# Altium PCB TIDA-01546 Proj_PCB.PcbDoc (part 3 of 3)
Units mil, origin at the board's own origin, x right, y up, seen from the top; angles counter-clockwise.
Board outline 2500 x 2000 mil, 2 copper layers (Top Layer, Bottom Layer), stack 62 mil thick; 176 components, 113 nets, 564 pads, 250 vias.
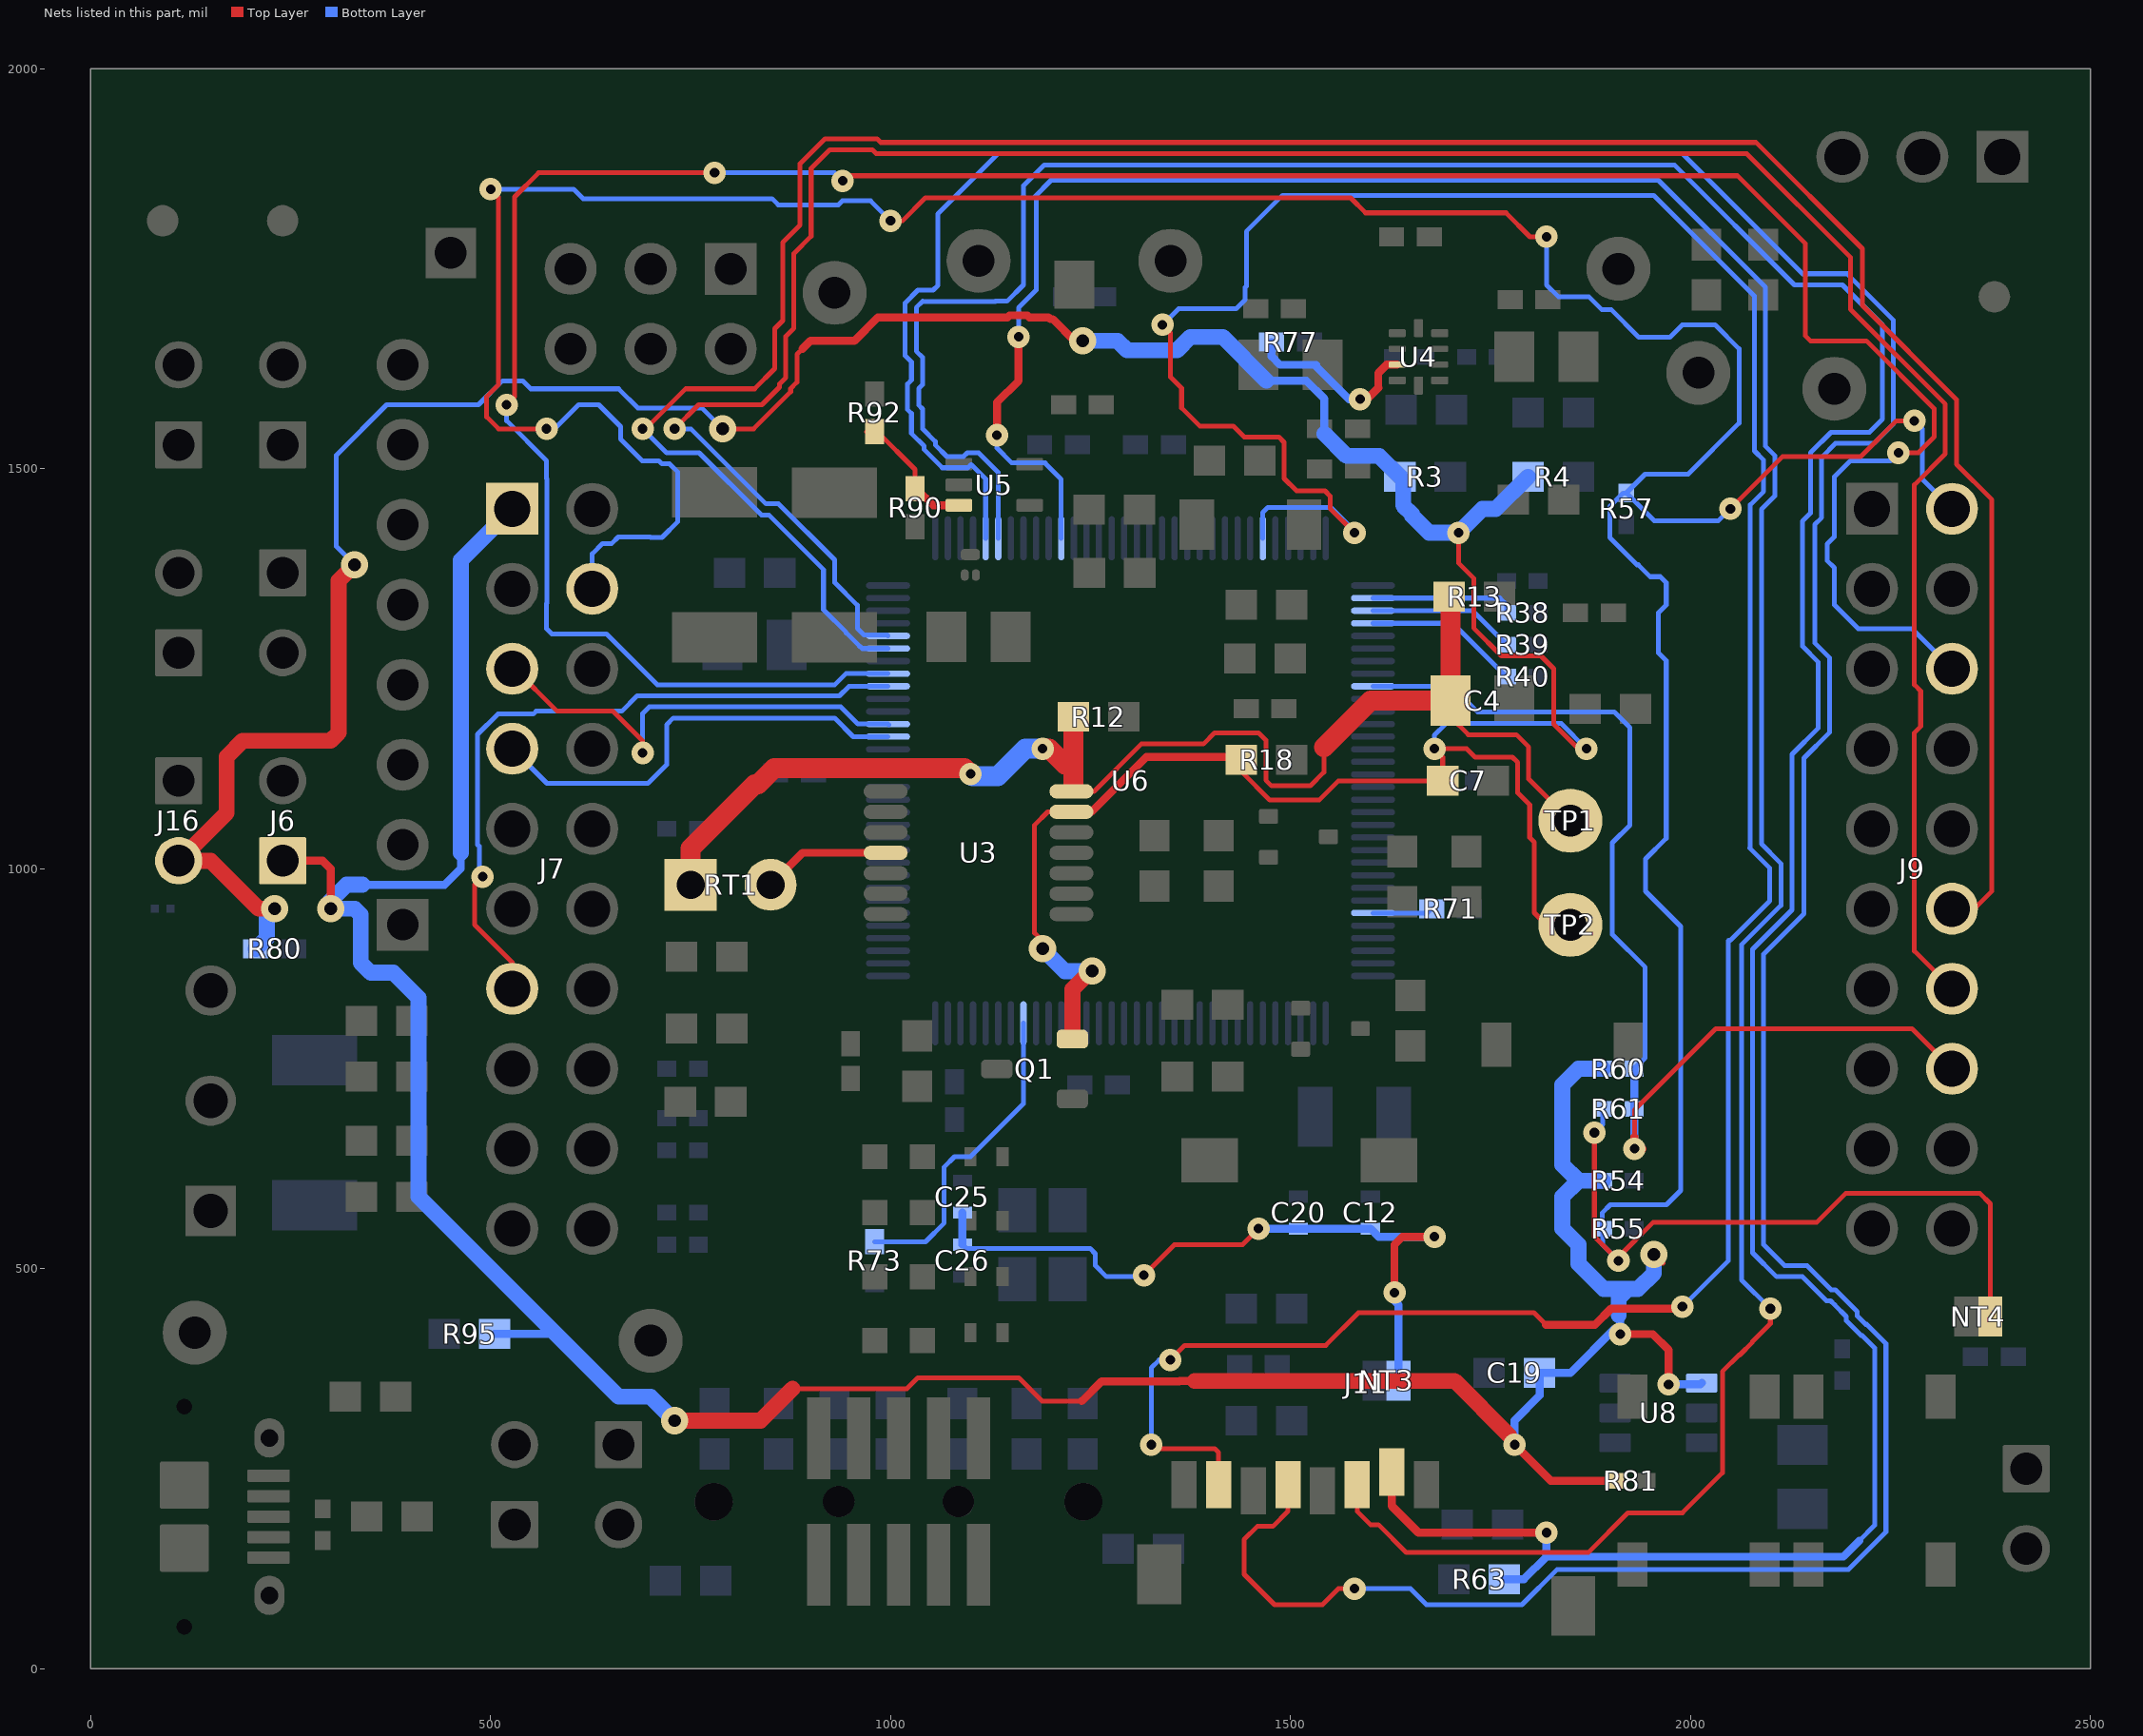
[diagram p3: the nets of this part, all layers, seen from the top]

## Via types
v1: diameter 28, hole 12, Top Layer to Bottom Layer, 217 vias
v2: diameter 34, hole 16, Top Layer to Bottom Layer, 30 vias
v3: diameter 50, hole 28, Top Layer to Bottom Layer, 3 vias

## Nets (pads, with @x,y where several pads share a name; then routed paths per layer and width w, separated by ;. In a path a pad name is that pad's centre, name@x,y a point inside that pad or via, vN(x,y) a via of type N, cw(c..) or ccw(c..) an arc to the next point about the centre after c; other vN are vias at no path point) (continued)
NetR38_1: R38.1 U6.34 | length 180.4
  Bottom Layer w6: U6.34@1603.15,1338.35 1761.65,1338.35 1770.32,1329.68 R38.1@1770.32,1320
NetR39_2: R39.2 U6.35 | length 184.8
  Bottom Layer w6: U6.35@1603.15,1322.6 1727.72,1322.6 R39.2@1770.31,1280
NetR40_1: R40.1 U6.36 | length 194.9
  Bottom Layer w6: U6.36@1603.15,1306.85 1703.15,1306.85 1770,1240 R40.1@1770.32,1240
NetR71_1: R71.1 U6.59 | length 75.4
  Bottom Layer w6: U6.59@1603.15,944.65 1671.02,944.65 R71.1@1676.38,950
NetR73_1: R73.1 U6.89 | length 399.3
  Bottom Layer w6: R73.1@980,533.62 1043.62,533.62 1067.13,557.13 1067.13,627.13 1080,640 1100,640 1166.14,706.14 U6.89@1166.14,806.85
NetR76_1: R77.2 U4.3 | length 223.4
  Top Layer w10: v1@1590,1590 1598.75,1590 1609.92,1601.17 1609.72,1601.37 1609.72,1619.57 1620.16,1630.01 1620.16,1630.16 U4.3@1633.43,1630.16
  Bottom Layer w10: R77.2@1476.38,1658.52 1476.38,1640.49 1486.87,1630 1532.35,1630 1532.35,1627.65 1573,1587 v1(1587,1587)
NetR90_2: R90.2 R92.2 U5.3 | length 167.7
  Top Layer w6: R92.2@970,1546.38 983.46,1546.38 1030.63,1499.21 R90.2@1030.63,1474.99
  Top Layer w10: R90.2@1030.63,1474.99 1032.6,1474.99 1053.18,1454.41 U5.3@1085.39,1454.41
NetRT1_2: RT1.2 U3.11 | length 160.4
  Top Layer w10: RT1.2@850,980 889.99,1019.99 U3.11@993.85,1019.99
REG25: C4.2 R12.1 R13.1 RT1.1 TP1.1 U3.7 | length 1684.1
  Top Layer w6: U3.7@1226.13,1096.76 1254.32,1096.76 1313.42,1155.87 1391.05,1155.87 1405.18,1170 1460,1170 1469.22,1160.78 1469.22,1110.78 1476.41,1103.59 1524.65,1103.59 1541.71,1120.66 1541.71,1151.71 ; C4.2@1700,1204.69 1700,1190 1722.37,1167.63 1782.37,1167.63 1797.88,1152.12 1797.88,1112.12 TP1.1@1850,1060
  Top Layer w10: 1218.5,1130 1228.5,1140
  Top Layer w25: RT1.1@750,980 750,1025.13 830.5,1105.63 834.24,1105.63 854.61,1126 1092.42,1126 v1(1100,1118.42) ; v1(1190,1150) 1198.5,1150 1218.5,1130 ; U3.7@1228.5,1102.78 1228.5,1140 R12.1@1228.5,1190 ; 1541.71,1151.71 1600,1210 C4.2@1700,1210 ; C4.2@1700,1204.69 C4.2@1700,1210 ; R13.1@1700,1340 C4.2@1700,1210
  Bottom Layer w25: v1(1100,1118.42) 1102.79,1115.63 1134.24,1115.63 1168.61,1150 v1(1190,1150)
REGIN: C7.2 J16.2 Q1.2 R3.1 R4.1 R18.1 R80.1 TP2.1 U3.6 | length 4627.6
  Top Layer w6: v2(790,1550) 828.75,1550 875.13,1596.38 875.13,1600.3 883,1608.18 883,1643 890,1650 ; v2(1190,900) 1190,909.6 1180,919.6 1180,1054.57 1196.61,1071.17 U3.6@1226.13,1071.17 ; R18.1@1438.66,1136.28 1438.66,1121.34 1474.28,1085.72 1535.72,1085.72 1560,1110 C7.2@1690.32,1110 1690.32,1139.68 v1(1680,1150) 1720.38,1150 1730.8,1139.57 1777.5,1139.57 1784.01,1133.07 1784.01,1095.12 1799.13,1080 1799.13,1038.93 1804.87,1033.18 1804.87,945.13 1820.18,929.82 TP2.1@1849.88,929.82 ; v1(1710,1420) 1710,1382.27 1729.06,1363.2 1729.06,1300.94 1763.78,1266.22 1812.99,1266.22 1829.1,1250.11 1829.1,1180.9 1860,1150 v1(1870,1150)
  Top Layer w10: 890,1650 900,1660 954.92,1660 984.18,1689.25 1146.25,1689.25 1148.87,1691.87 1171.13,1691.87 1173.75,1689.25 1197.54,1689.25 1199.67,1687.13 1202.87,1687.13 1230,1660 v2(1240,1660) ; U3.6@1226.13,1071.17 1251.17,1071.17 1320,1140 R18.1@1440,1140 ; v2@1250,871.97 v2(1251.97,871.97)
  Top Layer w20: v2(230,950) 210,950 150,1010 J16.2@110,1010 170,1070 170,1140 190,1160 300,1160 310,1170 310,1360 v2(330,1380) ; Q1.2@1227.24,787.09 1227.24,849.21 v2@1250,871.97
  Bottom Layer w6: v2(330,1380) 307.13,1402.87 307.13,1517.13 370,1580 484.82,1580 514.82,1610 540.04,1610 550.04,1600 660,1600 683.87,1576.13 763.87,1576.13 v2(790,1550) ; v1(1680,1150) 1680,1167 1694.46,1181.46 1838.54,1181.46 v1(1870,1150)
  Bottom Layer w10: 1470,1610 1520,1610 1542.28,1587.72 1542.28,1543.94
  Bottom Layer w20: R80.1@206.38,900 220,913.62 220,940 v2(230,950) ; v2(1190,900) 1218.03,871.97 v2(1251.97,871.97) ; v2(1240,1660) 1283.97,1660 1295.85,1648.13 1358.13,1648.13 1374.87,1664.87 1415.13,1664.87 1470,1610 ; 1542.28,1543.94 1570.18,1516.04 1610.81,1516.04 R3.1@1636.85,1490 1640.87,1485.98 1640.87,1454.2 1651.87,1443.2 1651.87,1441.54 1673.42,1420 v1(1710,1420) 1740,1450 1756.85,1450 R4.1@1796.85,1490
RESET: J9.16 R60.1 R61.1 U6.41 | length 1419.3
  Top Layer w6: 1930,665 1930,698.35 2031.65,800 2277,800 J9.16@2327,750
  Top Layer w10: 1930,665 v1(1930,650) v1@1940,650
  Bottom Layer w6: U6.41@1603.15,1228.11 1701.89,1228.11 1733.87,1196.13 1904.63,1196.13 1924.5,1176.25 1924.5,1054.5 1902.38,1032.38 1902.38,918 1943.46,876.91 1943.46,763.78 R60.1@1929.69,750
  Bottom Layer w10: R60.1@1929.69,750 R61.1@1929.68,700 1929.68,680.32 1930,680 v1(1930,650)
SD_SSI3_CLK: J11.5 U6.5 | length 4546
  Top Layer w6: J11.5@1496.77,230 1496.77,196.77 1477.87,177.87 1458.45,177.87 1442.13,161.55 1442.13,117.87 1480,80 1540,80 1560,100 v1(1580,100)
  Bottom Layer w6: U6.5@1118.9,1413.15 1118.9,1487.23 1100.86,1505.27 1096.84,1501.25 1064.74,1501.25 1042.04,1523.95 1042.04,1528.34 1026.13,1544.25 1026.13,1569.08 1021.25,1573.95 1021.25,1606.05 1026.13,1610.92 1026.13,1633.49 1018.25,1641.37 1018.25,1707.29 1034.25,1723.29 1053.29,1723.29 1059.13,1729.13 1059.13,1818.75 1134.56,1894.18 1989.69,1894.18 2140,1743.87 2195.75,1743.87 2253.87,1685.75 2253.87,1556.25 2229.44,1531.82 2181.44,1531.82 2164.05,1514.43 2164.05,1438.98 2155.4,1430.33 2155.4,1282.39 2173.87,1263.92 2173.87,1170.21 2141.83,1138.17 2141.83,943.64 2091.62,893.42 2091.62,530 2117.75,503.87 2145.75,503.87 2175.87,473.75 2181.05,473.75 2186.05,468.75 2208.75,446.05 2208.75,440.87 2219.19,430.43 2220.48,430.43 2244.46,406.45 2244.46,170.79 2197.8,124.13 1833.49,124.13 1789.36,80 1670,80 1650,100 v1(1580,100)
SD_SSI3_CS: J11.2 R63.2 U6.6 | length 4271.5
  Top Layer w10: J11.2@1626.69,245.75 1626.69,203.31 1660,170 v1(1820,170)
  Bottom Layer w6: U6.6@1134.65,1413.15 1134.65,1495.35 1110,1520 1095.96,1520 1091.09,1515.13 1070.48,1515.13 1055.91,1529.7 1055.91,1534.09 1040,1550 1040,1574.82 1035.13,1579.7 1035.13,1600.3 1040,1605.18 1040,1639.24 1032.13,1647.12 1032.13,1701.55 1040,1709.42 1040.29,1709.13 1131.07,1709.13 1131.37,1709.42 1145.55,1709.42 1166.13,1730 1166.13,1853.87 1192.25,1880 1980,1880 2130,1730 2190,1730 2240,1680 2240,1562 2223.69,1545.69 2175.69,1545.69 2150.18,1520.18 2150.18,1444.78 2140,1434.6 2140,1278.18 2160,1258.18 2160,1175.95 2127.08,1143.04 2127.08,948.51 2077.75,899.17 2077.75,520 2107.75,490 2140,490 2170.13,459.87 2175.3,459.87 2180.3,454.87 2194.87,440.3 2194.87,435.13 2213.44,416.56 2214.74,416.56 2230.59,400.71 2230.59,179.37 2211.22,160
  Bottom Layer w10: R63.2@1767.49,111.89 1791.89,111.89 1820,140 ; v1(1820,170) 1820,140 ; 2211.22,160 2191.22,140 1820,140
SD_SSI3_DAT0: J11.3 U6.11 | length 3600.2
  Top Layer w6: v1@1160,1660 v1(1160,1665) ; J11.3@1583.39,230 1583.39,196.61 1600,180 1610,180 1644.87,145.13 1872.33,145.13 1922.02,194.82 1990,194.82 2040,244.82 2040,371.41 2060.72,392.13 2061.55,392.13 2077.87,408.45 2077.87,409.28 2100,431.41 v1(2100,450)
  Top Layer w10: v1(1133,1542.02) 1133,1583 1160,1610 v1@1160,1660
  Bottom Layer w6: v1(1133,1542.02) 1133,1525.83 1151.51,1507.32 1193.53,1507.32 1193.53,1506.47 1213.39,1486.61 U6.11@1213.39,1413.15 ; v1(1160,1665) 1160,1701.42 1182,1723.42 1182,1840 ; 1180,1840 1200.76,1860.76 1960,1860.76 2093.87,1726.88 2093.87,1528.11 2105.39,1516.59 2105.39,1465.86 2088.75,1449.22 2088.75,1031.25 2099.92,1020.08 2099.92,1019.7 2113.21,1006.41 2113.21,954.25 2063.87,904.92 2063.87,486.13 v1(2100,450)
SD_SSI3_DAT1: J11.7 U6.27 | length 3764.8
  Top Layer w6: v1(1325.9,280) 1330.78,275.13 1405.19,275.13 1410.16,270.16 J11.7@1410.16,230 ; v1(1340,1680) 1350,1670 1350,1614.8 1363.87,1600.92 1363.87,1576.13 1386.55,1553.45 1428.44,1553.45 1442.31,1539.57 1485.69,1539.57 1492.06,1533.2 1492.06,1487.94 1507.63,1472.37 1543.09,1472.37 1549.46,1466 1549.46,1450.54 v1(1580,1420) ; v1(1349.67,385.93) 1367.86,404.13 1544.13,404.13 1585,445 1804.34,445 1819.34,430 ; v1@1990,450 v1(1990,452.5)
  Top Layer w10: 1819.34,430 1880.79,430 1900.79,450 v1@1990,450
  Bottom Layer w6: v1(1325.9,280) 1325.9,375.9 1335.93,385.93 v1(1349.67,385.93) ; v1(1340,1680) 1360,1700 1432,1700 1443.5,1711.5 1443.5,1726.95 1444.87,1728.32 1444.87,1796.73 1490,1841.86 1954.07,1841.86 2080,1715.93 2080,1522.36 2091.51,1510.85 2091.51,1471.61 2074.87,1454.96 2074.87,1027.13 2073.87,1026.13 2099.34,1000.66 2099.34,960 2050,910.66 ; U6.27@1465.35,1413.15 1465.35,1445.35 1471.58,1451.58 1550.23,1451.58 v1@1580,1421.81 ; v1(1990,452.5) 2047.5,510 2047.5,910.16 2048,910.66
SPI_CLK: J7.13 U6.120 | length 882.3
  Top Layer w6: v1(490,990) 480,980 480,930 527,883 J7.13@527,850
  Bottom Layer w6: v1(490,990) 485.69,994.31 485.69,1027.96 483.65,1030 483.65,1167.96 509.04,1193.35 553.35,1193.35 557,1197 664,1197 683.13,1216.13 936.13,1216.13 948.11,1228.11 U6.120@996.85,1228.11
SPI_CS1: J9.6 U6.121 | length 3537.4
  Top Layer w6: v1(520,1580) 530,1590 530,1840 560,1870 v1(780,1870) ; v1(940,1860) 946.37,1866.37 2058.91,1866.37 2143.87,1781.41 2143.87,1666.13 2150,1660 2220,1660 2304.87,1575.13 2304.87,1540 2284.87,1520 v1(2260,1520)
  Bottom Layer w6: v1(520,1580) 520,1560 570,1510 570,1487.69 570.35,1487.34 570.35,1332.04 570,1331.69 570,1300 576.65,1293.35 644.96,1293.35 708.31,1230 930.38,1230 944.24,1243.86 U6.121@996.85,1243.86 ; v1(780,1870) 930,1870 v1(940,1860) ; v1(2260,1520) 2250,1510 2200,1510 2180,1490 2180,1415.05 2170.9,1405.95 2170.9,1385.34 2180,1376.25 2180,1330 2210,1300 2277,1300 J9.6@2327,1250
SPI_MISO: J9.14 U6.124 | length 3220.3
  Top Layer w6: v1(730,1550) 760,1580 839.13,1580 861.25,1602.13 861.25,1606.05 869.13,1613.92 869.13,1648.75 869.13,1665.77 879.13,1675.77 879.13,1769.13 900.7,1790.7 900.7,1875.5 923.95,1898.75 977.34,1898.75 981.97,1894.12 2070.4,1894.12 2200,1764.52 2200,1699.62 2318.75,1580.87 2318.75,1518.75 2280,1480 2280,1230 2287.84,1222.16 2287.84,1177.84 2280,1170 2280,897 J9.14@2327,850
  Bottom Layer w6: v1(730,1550) 750.38,1550 844.25,1456.13 860,1456.13 930,1386.13 930,1357.95 958.42,1329.54 958.42,1300.72 967.09,1292.04 995.91,1292.04 U6.124@996.85,1291.1
SPI_MOSI: J9.12 U6.123 | length 3235
  Top Layer w6: v1@693.87,1550 743.87,1600 830,1600 855.25,1625.25 855.25,1675.25 865.25,1685.25 865.25,1782.97 886.82,1804.55 886.82,1881.24 918.2,1912.62 983.09,1912.62 987.72,1907.99 2082.01,1907.99 2215,1775 2215,1704.24 2332.62,1586.62 2332.62,1505.69 2377,1461.31 2377,972 2358,953 J9.12@2330,953
  Bottom Layer w6: v1(690,1550) 720,1520 760.76,1520 838.51,1442.25 847.75,1442.25 916.13,1373.87 916.13,1323.87 944.54,1295.46 944.54,1294.97 961.35,1278.17 961.83,1278.17 964.65,1275.35 U6.123@996.85,1275.35
SYS_GND: J7.4 J9.2 NT4.2 R55.1 R57.1 R61.2 | length 5384.6
  Top Layer w6: v1(500,1849.57) 510,1839.57 510,1605.18 495.13,1590.3 495.13,1564.87 510,1550 v1(570,1550) v1@575.02,1550 ; v1(1000,1810) 1014.82,1810 1043.44,1838.62 1575.25,1838.62 1593.87,1820 1769.52,1820 1799.52,1790 v1(1820,1790) ; v1(1880,670) 1880,540 v1(1910,510) 1910,514.57 1953.25,557.82 2157.82,557.82 2194.48,594.48 2361.72,594.48 2375,581.2 NT4.2@2375,440 ; v1(2050,1450) 2115,1515 2212.62,1515 2257.62,1560 v1(2280,1560)
  Bottom Layer w6: v1(500,1849.57) 603.79,1849.57 615.61,1837.75 851.87,1837.75 859.62,1830 934.82,1830 939.7,1834.87 969.87,1834.87 970,1835 975,1835 v1(1000,1810) v1@990,1810 ; v1(570,1550) 580,1550 610,1580 635.18,1580 662.59,1552.59 662.59,1537.03 689.62,1510 710.38,1510 714.25,1506.13 723.87,1506.13 734.07,1495.93 734.07,1434.07 714.23,1414.23 700,1414.23 699.36,1414.87 659.7,1414.87 651.47,1406.65 640,1406.65 627,1393.65 J7.4@627,1350 J7.4@620,1350 ; v1(1820,1790) 1820,1730 1834.82,1715.18 1872.88,1715.18 1888.93,1699.13 1900.87,1699.13 1935.67,1664.33 1974.33,1664.33 1990,1680 2030.87,1680 2060.87,1650 2060.87,1557.06 1997.17,1493.35 1943.35,1493.35 1920,1470 R57.1@1920,1469.68 ; v1(1880,670) 1890.31,680.31 R61.2@1890.31,700 ; v1(1910,510) 1890.32,529.68 R55.1@1890.32,550 1890,550.32 1890,570 1900,580 1970.05,580 1987.82,597.76 1987.82,927.87 1944.01,971.68 1944.01,1012.18 1969.77,1037.95 1969.77,1260.23 1960,1270 1960,1320 1969.77,1329.77 1969.77,1357.7 1962.35,1365.13 1949.7,1365.13 1934.82,1380 1933.28,1380 1899.28,1414 1899.28,1453.06 1915.91,1469.68 R57.1@1920,1469.68 ; v1(2050,1450) 2035.13,1435.13 1954.56,1435.13 R57.1@1920,1469.68 ; v1(2280,1560) 2290,1550 2290,1487 J9.2@2327,1450
SYS_VCC: C19.2 J6.1 J7.1 R54.1 R60.2 R81.2 R95.2 U8.1 | length 3919.3
  Top Layer w6: 877.45,350 1020.38,350 1034.11,363.73 1160.32,363.73 1189.6,334.45 1239.17,334.45 ; v2(1954.39,517.87) v2@1965.62,506.65
  Top Layer w10: J6.1@240,1010 290,1010 300,1000 v2(300,950) ; 1239.17,334.45 1263.78,359.06 1360.8,359.06 1361.49,359.75 1380.25,359.75 ; v1(1780.31,280) 1825.31,235 R81.2@1905.31,235 ; v1(1912.28,418.21) 1953.01,418.21 1972.7,398.52 v1(1972.7,355.36)
  Top Layer w20: v2(730,310) 837.45,310 877.45,350 ; 1380.25,359.75 1705.22,359.75 v1@1773.43,291.55
  Bottom Layer w10: 340,980 442.5,980 462.77,1000.27 462.77,1020 ; R95.2@505,418.7 578.7,418.7 580,420 ; v1(1780.31,280) 1780.31,310.31 1811.5,341.5 C19.2@1811.5,369.68 1850,369.68 v1@1905.4,425.09 ; 1910.31,441.79 1912.28,439.82 v1(1912.28,418.21) ; v1(1972.7,355.36) 2012.4,355.36 U8.1@2014.13,357.09
  Bottom Layer w20: 340,980 320,980 300,960 v2(300,950) 330,950 337.5,942.5 337.5,882.54 350.04,870 378.54,870 410,838.54 410,590 580,420 660,340 700,340 v2(730,310) ; 462.77,1020 462.77,1385.77 J7.1@527,1450 ; R54.1@1890.32,610 1860,610 ; R60.2@1890.32,750 1860,750 1840,730 1840,630 1860,610 ; 1910.31,441.79 1910.31,463.16 1921.7,474.55 ; v2(1954.39,517.87) 1954.39,494.39 1934.55,474.55 1921.7,474.55 ; 1860,610 1840,590 1840,550 1860,530 1860,506.27 1891.71,474.55 1921.7,474.55
UART_RX: J7.7 U6.116 | length 567.6
  Bottom Layer w6: J7.7@527,1143 J7.7@527,1150 570.35,1106.65 696.65,1106.65 720,1130 720,1180 728.38,1188.38 930,1188.38 953.26,1165.12 U6.116@996.85,1165.12
UART_TX: J7.5 U6.117 | length 585.1
  Top Layer w6: J7.5@527,1250 530,1250 583,1197 653,1197 690,1160 v1(690,1144.82)
  Bottom Layer w6: v1(690,1144.82) 690,1194 698.25,1202.25 937.75,1202.25 959.13,1180.87 U6.117@996.85,1180.87 U6.117@997.79,1179.93
XTAL_GND: C12.2 C20.1 C25.2 C26.2 NT3.1 | length 910.4
  Top Layer w6: v1(1316.72,491.75) 1354.98,530 1440,530 v1(1460,550)
  Top Layer w10: v1(1630,470) 1630,530 1640,540 v1(1680,540)
  Bottom Layer w6: C26.2@1090,530 1094.87,525.13 1249.62,525.13 1255.99,518.76 1255.99,504.01 1270,490 1314.98,490 v1(1316.72,491.75)
  Bottom Layer w10: C26.2@1090,530 C25.2@1090,570 ; v1(1460,550) C20.1@1510,550 C12.2@1600,550 1610,540 v1(1680,540) ; v1(1630,470) 1630,460 1635,455 NT3.1@1635,360
pads on no net: FID1.1 FID2.1 FID3.1 J7.2 J7.3 J7.6 J7.8 J7.10 J7.11 J7.12 J7.14 J7.16 J7.18 J7.20 J9.1 J9.3 J9.5 J9.7 J9.9 J9.10 J9.11 J9.13 J9.15 J9.17 J9.19 J12.1 J12.P7 J13.2 J13.3 J13.4 Q4.0 U6.1 U6.4 U6.9 U6.12 U6.13 U6.14 U6.15 U6.21 U6.22 U6.23 U6.24 U6.25 U6.29 U6.30 U6.31 U6.32 U6.42 U6.43 U6.44 U6.45 U6.46 U6.49 U6.50 U6.53 U6.54 U6.56 U6.57 U6.60 U6.61 U6.62 U6.63 U6.64 U6.65 U6.68 U6.81 U6.82 U6.83 U6.84 U6.85 U6.86 U6.91 U6.92 U6.93 U6.94 U6.95 U6.96 U6.102 U6.103 U6.104 U6.105 U6.106 U6.108 U6.109 U6.110 U6.111 U6.112 U6.118 U6.119 U6.125 U6.126 U6.127 U6.128 U8.3 Y2.2 Y2.4

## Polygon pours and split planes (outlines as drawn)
GND on Top Layer "Top Layer-No Net" (solid, pour order 1): 0,0 2490,0 2490,1990 0,1990
GND on Bottom Layer "Bottom Layer-No Net" (solid, pour order 4): 0,0 2500,0 2500,2000 0,2000

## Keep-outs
Keep-Out Layer:
  text ".Layer_Name" at 577,-858.49 h60

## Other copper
Top Layer:
  text "'.PRJ_Number'.PCB_Rev-" at 470,1940 h70.27
  text "UL94V-0" at 2360,60 h22.84
  text ".Layer_Name" at 577,-858.49 h60
Bottom Layer:
  text ".Layer_Name" at 577,-858.49 h60

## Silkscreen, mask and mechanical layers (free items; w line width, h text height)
Top Overlay:
  region: 350,1980 50,1980 50,1880 350,1880
  text ".Layer_Name" at 577,-858.49 h60
Bottom Overlay:
  text ".Layer_Name" at 577,-858.49 h60
Top Paste:
  text ".Layer_Name" at 577,-858.49 h60
Bottom Paste:
  text ".Layer_Name" at 577,-858.49 h60
Top Solder:
  text ".Layer_Name" at 577,-858.49 h60
  text ".Layer_Name" at 577,-858.49 h60
Bottom Solder:
  text ".Layer_Name" at 577,-858.49 h60
Drill Guide:
  text ".Layer_Name" at 577,-858.49 h60
M1 Board Outline:
  lines w10: 0,1990 0,0 2500,0 2500,2000 0,2000
  text ".Layer_Name" at 577,-858.49 h60
M2 Board Dimensions:
  rectangle: 125,-400 500,-275
  rectangle: 0,-275 125,-150
  lines w7: 0,-275 1000,-275 ; 125,-400 125,-150 ; 250,-400 250,-150 ; 500,-400 500,-150 ; 750,-400 750,-150 ; 0,-400 0,-150 1000,-150 1000,-400 0,-400
  text ".Layer_Name" at 577,-858.49 h60
M3 3D STEP Top:
  text ".Layer_Name" at 577,-858.49 h60
M4 3D STEP Bottom:
  text ".Layer_Name" at 577,-858.49 h60
M5 Assembly Top:
  lines w10: -292,-930.17 6308,-930.17 ; -292,-726.83 6310,-726.83 ; -292,-523.5 -292,-1133.5 3713,-1133.5 6310,-1133.5 6310,-523.5 -291.5,-523.5 -291.5,-1133.5 1284,-1133.5 ; 2173,-1133.5 2173,-523.5 ; 3440,-726.83 3440,-523.5 ; 4280,-726.83 4280,-523.5 ; 4902,-1140 4902,-937.17
  text "COMPONENTS MARKED 'DNP' SHOULD NOT BE POPULATED." at 1153.5,-318.5 h60
  text "ASSEMBLY VARIANT:" at 1153,-434 h60
  text ".VariantName" at 2189,-434 h60
  text "PCB VIEWED FROM TOP SIDE" at -228.5,-655.67 h60
  text "BOARD #:" at 2248,-655.67 h60
  text ".PRJ_Number" at 2793.5,-655.67 h60
  text "REV:" at 3638,-655.67 h60
  text ".PCB_Rev" at 3929.5,-655.67 h60
  text "SVN REV:" at 4476,-655.67 h60
  text ".VersionControl_RevNumber" at 4982,-655.67 h60
  text "TID #:" at 2248,-859 h60
  text ".TID" at 2793.5,-859 h60
  text "PLOT NAME =" at -228.5,-1064.34 h60
  text ".plot_File_Name" at 577,-1064.34 h60
  text "GENERATED    :" at 2250,-1064.34 h60
  text ".Print_Date" at 3119.5,-1064.34 h60
  text ".Print_Time" at 3848.5,-1064.34 h60
  text "TEXAS INSTRUMENTS" at 5113,-1064.34 h60
M6 Assembly Bottom:
  lines w10: -292.5,-727.33 6309.5,-727.33 ; -290.5,-930.67 6309.5,-930.67 ; 1115.5,-1140.5 1115.5,-937.67 ; 1737.5,-727.33 1737.5,-524 ; 2577.5,-727.33 2577.5,-524 ; 3844.5,-1134 3844.5,-524 ; 4733.5,-1134 6309,-1134 6309,-524 -292.5,-524 -292.5,-1134 2304.5,-1134 6309.5,-1134 6309.5,-524
  text "COMPONENTS MARKED 'DNP' SHOULD NOT BE POPULATED." at 6102,-318 h60
  text ".VariantName" at 5058,-434 h60
  text "ASSEMBLY VARIANT:" at 6097,-434 h60
  text ".VersionControl_RevNumber" at 1035.5,-656.17 h60
  text "SVN REV:" at 1541.5,-656.17 h60
  text ".PCB_Rev" at 2088,-656.17 h60
  text "REV:" at 2379.5,-656.17 h60
  text ".PRJ_Number" at 3224,-656.17 h60
  text "BOARD #:" at 3769.5,-656.17 h60
  text "PCB VIEWED FROM BOTTOM SIDE" at 6246,-656.17 h60
  text ".TID" at 3224,-859.5 h60
  text "TID #:" at 3769.5,-859.5 h60
  text "TEXAS INSTRUMENTS" at 904.5,-1064.84 h60
  text ".Print_Time" at 2169,-1064.84 h60
  text ".Print_Date" at 2898,-1064.84 h60
  text "GENERATED    :" at 3767.5,-1064.84 h60
  text ".plot_File_Name" at 5440.5,-1064.84 h60
  text "PLOT NAME =" at 6246,-1064.84 h60
M9 Title Sheet:
  drawing of 57 lines, arcs and shapes, not listed
  text "1" at 739.84,8036.5 h70
  text "2" at 3235.5,8036.5 h70
  text "3" at 5724.84,8036.5 h70
  text "4" at 8231.51,8036.5 h70
  text "5" at 10730.5,8036.5 h70
  text "6" at 13235.5,8036.5 h70
  text "A" at -416.5,6893.5 h70
  text "A" at 14383.5,6893.5 h70
  text "B" at -416.5,4513.5 h70
  text "B" at 14383.5,4513.5 h70
  text "C" at -416.5,2138.5 h70
  text "C" at 14383.5,2138.5 h70
  text "PROJECT TITLE:" at 11343.5,277.5 h45
  text ".PRJ_Title" at 11393.5,144.17 h70
  text "DESIGNED FOR:" at 11343.5,-23.5 h45
  text ".PRJ_Customer" at 11393.5,-163.5 h70
  text "D" at -416.5,-231.5 h70
  text "D" at 14383.5,-231.5 h70
  text "FILE NAME:" at 11343.5,-323.5 h45
  text ".PCB_File_Name_No_Path" at 11393.5,-443.5 h70
  text "Texas Instruments (TI) and/or its licensors do not warrant the accuracy or completeness of this specification" at 6374,-605.34 h45
  text "ENGINEER:" at 11343.5,-613.5 h45
  text "LAYOUT BY:" at 12848.5,-613.5 h45
  text "or any information contained therein. TI and/or its licensors do not warrant that this design will meet" at 6329.01,-718 h45
  text ".PRJ_Engineer" at 11393.5,-768.49 h70
  text ".PCB_Layout" at 12899,-768.49 h70
  text "the specifications, will be suitable for your application or fit for any particular purpose, or will operate in" at 6329.01,-830.67 h45
  text ".Layer_Name" at 577,-858.49 h60
  text "ALTIUM DESIGNER VERSION:" at 12848.5,-923.5 h45
  text "an implementation. TI and/or its licensors do not warrant that the design is production worthy. You should" at 6329.01,-943.33 h45
  text "completely validate and test your design implementation to confirm the system functionality for your application." at 6374,-1056 h45
  text ".print_Scale" at 11393.5,-1056.83 h70
  text ".Application_BuildNumber" at 12899,-1056.83 h70
  text "1" at 739.84,-1263.5 h70
  text "2" at 3235.5,-1263.5 h70
  text "3" at 5724.84,-1263.5 h70
  text "4" at 8231.51,-1263.5 h70
  text "5" at 10730.5,-1263.5 h70
  text "6" at 13235.5,-1263.5 h70
M10 Fab Notes:
  drawing of 189 lines, arcs and shapes, not listed
  text "DESIGN INFORMATION" at 12382.02,6356.17 h60
  text "MIN. TRACK WIDTH:" at 11737.46,6224.05 h60
  text "8" at 12833.7,6224.05 h60
  text "MIL" at 12988.46,6224.05 h60
  text "MIN. CLEARANCE:" at 11737.46,6099.92 h60
  text "0.2" at 12773.7,6099.93 h60
  text "mm" at 12988.46,6099.92 h60
  text "MIN. VIA PAD SIZE:" at 11737.46,5975.8 h60
  text "24" at 12803.71,5975.8 h60
  text "MIL" at 12988.46,5975.8 h60
  text "0.05mm (2MIL)" at 12432.46,5845.9 h60
  text "MINIMUM ANNULAR RING" at 11408.23,5837.67 h60
  text "EXTERNAL" at 13140.46,5837.67 h60
  text "PER" at 11608.23,5727.55 h60
  text "IPC-D-275 CLASS 2 LEVEL C" at 11828.23,5727.54 h60
  text "MIL, HOLES" at 13316.46,5627.07 h60
  text "+/-" at 12924,5618.48 h60
  text "+/-" at 13778,5618.48 h60
  text "REGISTRATION TOLERANCES:" at 11408.23,5617.42 h60
  text "METAL" at 12608,5617.42 h60
  text "5" at 13184.2,5617.42 h60
  text "3" at 14017.2,5617.42 h60
  text "MIL" at 14133.46,5617.42 h60
  text "HOLE SIZE TOLERANCE (UNLESS OTHERWISE SPECIFIED):" at 11408.23,5519.1 h60
  text "+/-" at 13778,5516.23 h60
  text "3" at 14017.2,5515.17 h60
  text "MIL" at 14133.46,5515.17 h60
  text "MATERIAL:" at 11333.46,5377.52 h60
  text "FR-4 High Tg" at 12319.9,5249 h60
  text "X" at 12175.46,5241.01 h60
  text "FR-408" at 11754.46,5236.49 h60
  text "OTHER" at 13242.46,5236.49 h60
  text "62 MIL (1.6mm) +/-10%" at 12074.56,5093.46 h60
  text "X" at 11954.46,5091.01 h60
  text "THICKNESS:" at 11408.23,5085.24 h60
  text "OTHER" at 13359.46,5085.24 h60
  text "TOLERANCE:" at 11408.23,4946.92 h60
  text "X" at 12256.46,4946.92 h60
  text "ANSI IPC-6012 TYPE 3 CLASS 2" at 12434.48,4946.92 h60
  text "OTHER +/-" at 12434.46,4802.73 h60
  text "BOW & TWIST:" at 11408.23,4657.54 h60
  text "X" at 12256.46,4657.54 h60
  text "ANSI IPC-6012 TYPE 3 CLASS 2" at 12434.48,4657.54 h60
  text "OTHER +/-" at 12434.46,4510.85 h60
  text "DRILLING:" at 11333.46,4380.23 h60
  text "NC_DRILL FILES" at 13094.46,4275.04 h60
  text "REFERENCE:" at 11408.23,4271.1 h60
  text "X" at 12065.46,4271.01 h60
  text "AS SHOWN" at 12243.46,4271.1 h60
  text "X" at 12966.46,4271.1 h60
  text "OTHER" at 13392.46,4128.85 h60
  text "PTH COPPER THICKNESS:" at 11407.91,4125.32 h60
  text "X" at 12547.14,4125.32 h60
  text "20-30 um" at 12675.14,4125.32 h60
  text "BOARD FINISH:" at 11333.46,3977.73 h60
  text "SILKSCREEN:" at 11488.68,3867.6 h60
  text "X" at 12446.46,3867.6 h60
  text "TOP" at 12563.46,3867.6 h60
  text "X" at 12956.46,3867.6 h60
  text "BOTTOM" at 13074.46,3867.6 h60
  text "SILKSCREEN COLOR:" at 11488.68,3712.41 h60
  text "X" at 12445.46,3712.41 h60
  text "WHITE" at 12563.46,3712.41 h60
  text "OTHER" at 13074.46,3712.41 h60
  text "X" at 12576.46,3568.96 h60
  text "GREEN" at 12694.46,3568.96 h60
  text "OTHER" at 13312.46,3568.96 h60
  text "SOLDER RESIST COLOR:" at 11488.68,3562.1 h60
  text "X" at 12576.46,3414.71 h60
  text "MATTE" at 12694.46,3414.71 h60
  text "SEMI-GLOSS" at 13312,3414.07 h60
  text "IMMERSION GOLD (ENIG)" at 12394.46,3241.94 h60
  text "ENEPIG" at 13732,3234.72 h60
  text "SURFACE FINISH:" at 11333.46,3233.72 h60
  text "X" at 12216.46,3233.72 h60
  text "IMM. TIN/SILVER OR EQUIV" at 11663,3096.4 h60
  text "OTHER" at 13094.46,3092.47 h60
  text "ARRAY/PANEL:" at 11333.46,2937.09 h60
  text "CUT AND TRIM PER M1 BOARD OUTLINE" at 12394.46,2928.87 h60
  text "N.C. ROUTE" at 12394.46,2792.9 h60
  text "X" at 13082.46,2792.9 h60
  text "V. SCORE" at 13260.46,2792.9 h60
  text "CERTIFICATION:" at 11333.46,2663.77 h60
  text "MATERIALS AND WORKMANSHIP FOR ALL PCBS" at 12058.46,2663.77 h60
  text "TO MEET OR EXCEED THE REQUIREMENTS OF:" at 12058.46,2569.71 h60
  text "X" at 11695.97,2441.08 h60
  text "ANSI IPC-A-600F CLASS ->" at 11823.96,2441.08 h60
  text "X" at 13471.97,2441.08 h60
  text "2" at 13581.96,2441.08 h60
  text "1" at 13266.96,2439.58 h60
  text "3" at 13935.96,2439.58 h60
  text "X" at 12507.97,2293.39 h60
  text "RoHS" at 12635.96,2293.39 h60
  text "OTHER" at 13280.36,2293.39 h60
  text "PER ORDER" at 13677.42,2293.39 h60
  text "ALL BOARDS MUST MEET OR EXCEED UL94-V0 REQUIREMENTS." at 11361,2139.57 h60
  text "PCB MUST BEAR THE UL94V-0 UL REGISTERED MATERIAL ID NUMBER" at 11361,2023.5 h60
  text "ADDITIONAL REQUIREMENTS:" at 11333.46,1854.08 h60
  text "MICROSECTION:" at 11408.23,1746.95 h60
  text "YES" at 12313.96,1746.95 h60
  text "REQUIRED" at 13175.46,1602.62 h60
  text "BARE BOARD ELEC. TEST:" at 11408.23,1599.76 h60
  text "NONE" at 12713.96,1599.76 h60
  text "X" at 13057.46,1599.76 h60
  text "PER ORDER" at 13767.46,1599.76 h60
  text "XX MIL VIAS REQUIRE NON-CONDUCTIVE FILL AND PLANARIZE" at 11576.38,1394.82 h59
  text "XX MIL VIAS REQUIRE CONDUCTIVE FILL AND PLANARIZE" at 11584.38,1290.84 h60
  text "OUTER XX MIL VIAS REQUIRE 50 OHM SINGLE-ENDED IMPEDANCE" at 11583.39,1127.46 h58
  text "LAYER 2 & 3 (INNER LAYERS) XX MIL WIDE, XX MIL SPACE / TRACES REQUIRE 100 OHM DIFFERENTIAL IMPEDANCE" at 11575.39,891.74 h60
  text ".Layer_Name" at 577,-858.49 h60
M11 Gerber Information:
  lines w10: -292,-930.17 6308,-930.17 ; -292,-726.83 6310,-726.83 ; -292,-523.5 -292,-1133.5 3713,-1133.5 6310,-1133.5 6310,-523.5 -291.5,-523.5 -291.5,-1133.5 1284,-1133.5 ; 2173,-1133.5 2173,-523.5 ; 3440,-726.83 3440,-523.5 ; 4280,-726.83 4280,-523.5 ; 4902,-1140 4902,-937.17
  text "ALL ARTWORK VIEWED FROM TOP SIDE" at -228.5,-655.67 h60
  text "BOARD #:" at 2248,-655.67 h60
  text ".PRJ_Number" at 2793.5,-655.67 h60
  text "REV:" at 3638,-655.67 h60
  text ".PCB_Rev" at 3929.5,-655.67 h60
  text "SVN REV:" at 4476,-655.67 h60
  text ".VersionControl_RevNumber" at 4982,-655.67 h60
  text "LAYER NAME =" at -228.5,-858.49 h60
  text "TID #:" at 2248,-859 h60
  text ".TID" at 2793.5,-859 h60
  text "PLOT NAME =" at -228.5,-1064.34 h60
  text ".plot_File_Name" at 577,-1064.34 h60
  text "GENERATED    :" at 2250,-1064.34 h60
  text ".Print_Date" at 3119.5,-1064.34 h60
  text ".Print_Time" at 3848.5,-1064.34 h60
  text "TEXAS INSTRUMENTS" at 5113,-1064.34 h60
M12 Stackup:
  drawing of 191 lines, arcs and shapes, not listed
  text "Layer" at 9790.34,7830 h60
  text "Name" at 10200.26,7830 h60
  text "Material" at 11130,7830 h60
  text "Thickness" at 11989.77,7830 h60
  text "Constant" at 12639.6,7830 h60
  text "Board Layer Stack" at 13209.46,7830 h60
  text "1" at 9790.34,7710 h60
  text "Top Overlay" at 10200.26,7710 h60
  text "2" at 9790.34,7590 h60
  text "Top Solder" at 10200.26,7590 h60
  text "Solder Resist" at 11130,7590 h60
  text "0.40mil" at 11989.77,7590 h60
  text "3.5" at 12639.6,7590 h60
  text "3" at 9790.34,7470 h60
  text "Top Layer" at 10200.26,7470 h60
  text "Copper" at 11130,7470 h60
  text "1.40mil" at 11989.77,7470 h60
  text "4" at 9790.34,7350 h60
  text "Dielectric1" at 10200.26,7350 h60
  text "FR-4" at 11130,7350 h60
  text "59.20mil" at 11989.77,7350 h60
  text "4.8" at 12639.6,7350 h60
  text "5" at 9790.34,7230 h60
  text "Bottom Layer" at 10200.26,7230 h60
  text "Copper" at 11130,7230 h60
  text "1.40mil" at 11989.77,7230 h60
  text "6" at 9790.34,7110 h60
  text "Bottom Solder" at 10200.26,7110 h60
  text "Solder Resist" at 11130,7110 h60
  text "0.40mil" at 11989.77,7110 h60
  text "3.5" at 12639.6,7110 h60
  text "7" at 9790.34,6990 h60
  text "Bottom Overlay" at 10200.26,6990 h60
  text ".Layer_Name" at 577,-858.49 h60
M13 Component Bodies Top:
  text ".Layer_Name" at 577,-858.49 h60
M14 Component Bodies Bottom:
  text ".Layer_Name" at 577,-858.49 h60
M15 Courtyards Top:
  text ".Layer_Name" at 577,-858.49 h60
M16 Courtyards Bottom:
  text ".Layer_Name" at 577,-858.49 h60
Drill Drawing:
  circle w10: c4418.72,1419.18 r22.07
  lines w10: 4396.65,503.23 4418.72,514.27 4440.79,503.23 4429.75,525.3 4440.79,547.37 4418.72,536.34 4396.65,547.37 4407.68,525.3 4396.65,503.23 ; 4396.65,613.59 4407.68,613.59 4418.72,602.55 4429.75,613.59 4440.79,613.59 4429.75,624.62 4440.79,635.66 4429.75,635.66 4418.72,646.69 4407.68,635.66 4396.65,635.66 4407.68,624.62 4396.65,613.59 ; 4396.65,701.87 4418.72,712.91 4440.79,701.87 4429.75,723.94 4440.79,746.01 4418.72,734.98 4396.65,746.01 4407.68,723.94 4396.65,701.87 ; 4396.65,845.33 4440.79,845.33 4418.72,801.19 4396.65,845.33 ; 4396.65,911.55 4407.68,911.55 4407.68,900.51 4429.75,900.51 4429.75,911.55 4440.79,911.55 4440.79,933.62 4429.75,933.62 4429.75,944.65 4407.68,944.65 4407.68,933.62 4396.65,933.62 4396.65,911.55 ; 4396.65,1010.87 4407.68,1010.87 4418.72,999.83 4429.75,1010.87 4440.79,1010.87 4429.75,1021.9 4440.79,1032.94 4429.75,1032.94 4418.72,1043.97 4407.68,1032.94 4396.65,1032.94 4407.68,1021.9 4396.65,1010.87 ; 4396.65,1110.19 4407.68,1110.19 4407.68,1099.15 4429.75,1099.15 4429.75,1110.19 4440.79,1110.19 4440.79,1132.26 4429.75,1132.26 4429.75,1143.29 4407.68,1143.29 4407.68,1132.26 4396.65,1132.26 4396.65,1110.19 ; 4396.65,1198.47 4440.79,1198.47 4440.79,1242.61 4396.65,1242.61 4396.65,1198.47 ; 4396.65,1297.79 4440.79,1297.79 4440.79,1341.93 4396.65,1341.93 4396.65,1297.79 ; 4396.65,1540.57 4440.79,1540.57 4418.72,1496.43 4396.65,1540.57 ; 4405.47,512.06 4418.72,518.68 4431.96,512.06 4425.34,525.3 4431.96,538.54 4418.72,531.92 4405.47,538.54 4412.1,525.3 4405.47,512.06 ; 4405.47,618 4412.1,618 4418.72,611.38 4425.34,618 4431.96,618 4425.34,624.62 4431.96,631.24 4425.34,631.24 4418.72,637.86 4412.1,631.24 4405.47,631.24 4412.1,624.62 4405.47,618 ; 4405.47,915.96 4412.1,915.96 4412.1,909.34 4425.34,909.34 4425.34,915.96 4431.96,915.96 4431.96,929.2 4425.34,929.2 4425.34,935.82 4412.1,935.82 4412.1,929.2 4405.47,929.2 4405.47,915.96 ; 4405.47,1207.3 4431.96,1207.3 4431.96,1233.78 4405.47,1233.78 4405.47,1207.3 ; 4405.47,1531.74 4431.96,1531.74 4418.72,1505.26 4405.47,1531.74
  lines w12: 4356,473.43 7467.21,473.43 ; 4356,1565.95 7467.21,1565.95 ; 4671.49,374.11 4671.49,1665.27 ; 4988.58,374.11 4988.58,1665.27 ; 5610.22,374.11 5610.22,1665.27 ; 5854.41,374.11 5854.41,1665.27 ; 6214.66,374.11 6214.66,1665.27 ; 6923.12,374.11 6923.12,1665.27 ; 4356,374.11 7467.21,374.11 7467.21,1665.27 4356,1665.27 4356,374.11
  text "Symbol" at 4415.59,1595.75 h72
  text "Quantity" at 4701.28,1595.75 h72
  text "Finished Hole Size" at 5018.38,1595.75 h72
  text "Plated" at 5640.02,1595.75 h72
  text "Hole Type" at 5884.21,1595.75 h72
  text "Drill Layer Pair" at 6244.45,1595.75 h72
  text "Hole Tolerance" at 6952.92,1595.75 h72
  text "217" at 4701.28,1496.43 h60
  text "12.00mil (0.305mm)" at 5018.38,1496.43 h60
  text "PTH" at 5640.02,1496.43 h60
  text "Round" at 5884.21,1496.43 h60
  text "Top Layer - Bottom Layer" at 6244.45,1496.43 h60
  text "30" at 4701.28,1397.11 h60
  text "16.00mil (0.406mm)" at 5018.38,1397.11 h60
  text "PTH" at 5640.02,1397.11 h60
  text "Round" at 5884.21,1397.11 h60
  text "Top Layer - Bottom Layer" at 6244.45,1397.11 h60
  text "3" at 4701.28,1297.79 h60
  text "28.00mil (0.711mm)" at 5018.38,1297.79 h60
  text "PTH" at 5640.02,1297.79 h60
  text "Round" at 5884.21,1297.79 h60
  text "Top Layer - Bottom Layer" at 6244.45,1297.79 h60
  text "2" at 4701.28,1198.47 h60
  text "35.00mil (0.889mm)" at 5018.38,1198.47 h60
  text "PTH" at 5640.02,1198.47 h60
  text "Round" at 5884.21,1198.47 h60
  text "Top Layer - Bottom Layer" at 6244.45,1198.47 h60
  text "11" at 4701.28,1099.15 h60
  text "39.37mil (1.000mm)" at 5018.38,1099.15 h60
  text "PTH" at 5640.02,1099.15 h60
  text "Round" at 5884.21,1099.15 h60
  text "Top Layer - Bottom Layer" at 6244.45,1099.15 h60
  text "34" at 4701.28,999.83 h60
  text "40.00mil (1.016mm)" at 5018.38,999.83 h60
  text "PTH" at 5640.02,999.83 h60
  text "Round" at 5884.21,999.83 h60
  text "Top Layer - Bottom Layer" at 6244.45,999.83 h60
  text "3" at 4701.28,900.51 h60
  text "43.31mil (1.100mm)" at 5018.38,900.51 h60
  text "PTH" at 5640.02,900.51 h60
  text "Round" at 5884.21,900.51 h60
  text "Top Layer - Bottom Layer" at 6244.45,900.51 h60
  text "43" at 4701.28,801.19 h60
  text "45.28mil (1.150mm)" at 5018.38,801.19 h60
  text "PTH" at 5640.02,801.19 h60
  text "Round" at 5884.21,801.19 h60
  text "Top Layer - Bottom Layer" at 6244.45,801.19 h60
  text "2" at 4701.28,701.87 h60
  text "47.24mil (1.200mm)" at 5018.38,701.87 h60
  text "PTH" at 5640.02,701.87 h60
  text "Round" at 5884.21,701.87 h60
  text "Top Layer - Bottom Layer" at 6244.45,701.87 h60
  text "2" at 4701.28,602.55 h60
  text "19.69mil (0.500mm)" at 5018.38,602.55 h60
  text "PTH" at 5640.02,602.55 h60
  text "Slot" at 5884.21,602.55 h60
  text "Top Layer - Bottom Layer" at 6244.45,602.55 h60
  text "+/-1.97mil" at 6952.92,602.55 h60
  text "2" at 4701.28,503.23 h60
  text "21.65mil (0.550mm)" at 5018.38,503.23 h60
  text "PTH" at 5640.02,503.23 h60
  text "Slot" at 5884.21,503.23 h60
  text "Top Layer - Bottom Layer" at 6244.45,503.23 h60
  text "+/-1.97mil" at 6952.92,503.23 h60
  text "349 Total" at 4701.28,403.91 h60
  text "Slot definitions :" at 4415.59,324.44 h60
  text "Routed Path Length" at 4858.14,324.44 h60
  text "= Calculated from tool start centre position to tool end centre position." at 5389.59,324.44 h60
  text "Hole Length" at 4858.14,274.77 h60
  text "= Routed Path Length + Tool Size = Slot length as defined in the PCB layout" at 5190.08,274.77 h60
  text ".Layer_Name" at 577,-858.49 h60
M17 Embedded Cavity:
  text ".Layer_Name" at 577,-858.49 h60
M18 Embedded Assembly:
  text ".Layer_Name" at 577,-858.49 h60
M19 Embedded Keepout:
  text ".Layer_Name" at 577,-858.49 h60

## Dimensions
0,0 to 2500,0 on M2 Board Dimensions
0,0 to 0,2000 on M2 Board Dimensions
0,-400 to 1000,-400 on M2 Board Dimensions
